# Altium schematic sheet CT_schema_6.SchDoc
size 145 x 123 mm
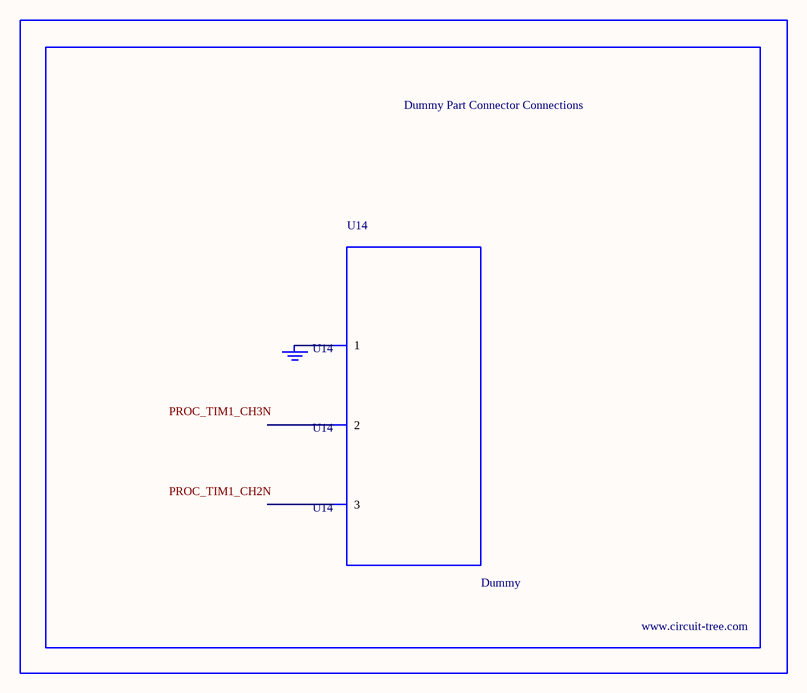
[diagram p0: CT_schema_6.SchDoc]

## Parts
BORDER5  (no value)
GND_INSTANCE_5_0  (no value)
U14  Dummy  [DUMMY_PACKAGE_149]

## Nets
NetGND_INSTANCE_5_0_0: GND_INSTANCE_5_0.0(GND) U14.1

Not connected (* = marked no-connect by the designer): U14 2 3

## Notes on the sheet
- Labels drawn without touching a wire or pin: PROC_TIM1_CH2N, PROC_TIM1_CH3N

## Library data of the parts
BORDER5 = BORDER_PAGE5
GND_INSTANCE_5_0 = GND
